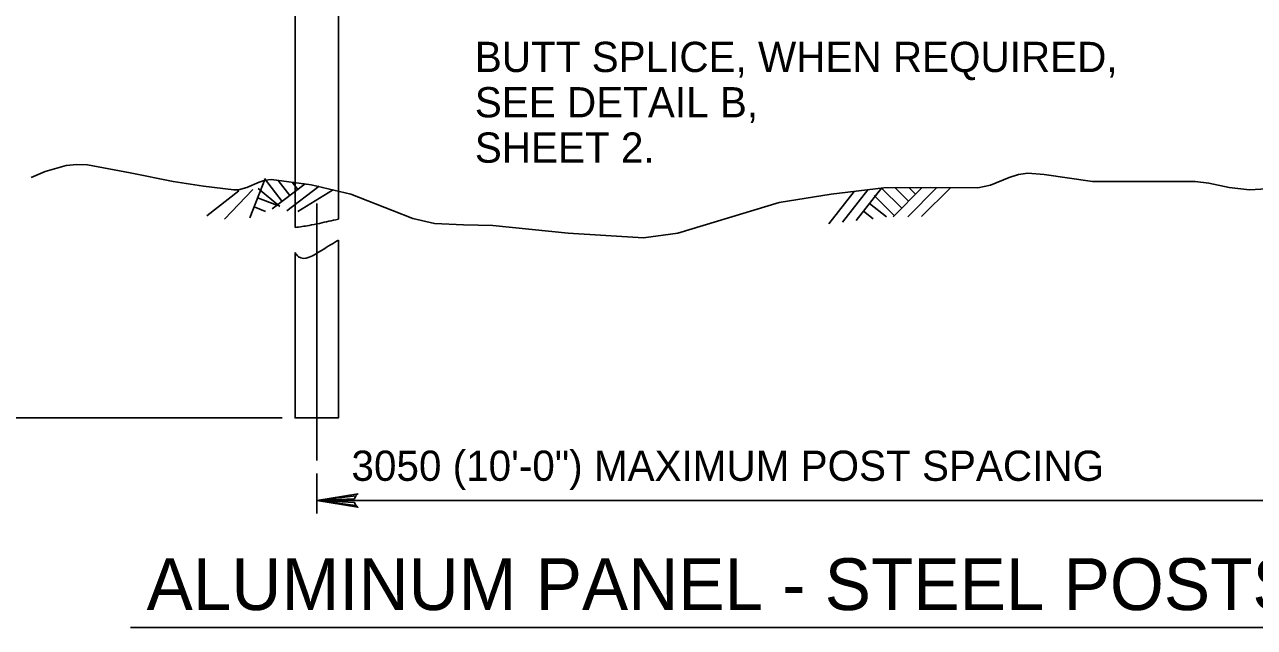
# Model space of a CAD drawing. Extents: x -4 to 901, y -468 to 720.
# Drawn here: x 119.8 to 256.4, y 539.9 to 606.9 of the extents above; entities that cross this region are included whole.
import ezdxf

# ---------------------------------------------------------------- set-up
doc = ezdxf.new("R2010")
doc.units = 0
doc.layers.add('2', color=7, linetype='Continuous')
doc.layers.add('3', color=7, linetype='Continuous')

msp = doc.modelspace()

# ---------------------------------------------------------------- linework, layer by layer
at = {"layer": '2'}
for p, q in [((144.8465, 585.443125), (146.5025, 589.703125)), ((146.4605, 589.811125), (148.4265, 587.255125)), ((147.3445, 586.437125), (150.9865, 589.237125)), ((148.0025, 589.609125), (149.2845, 587.943125)), ((148.9725, 586.225125), (152.5565, 588.981125)), ((149.5625, 589.407125), (150.1725, 588.611125)), ((214.9625, 588.779125), (217.2585, 586.513125)), ((216.2965, 585.555125), (219.5225, 588.827125)), ((216.5165, 588.789125), (218.0125, 587.313125)), ((217.9385, 585.567125), (221.1145, 588.785125)), ((218.0885, 588.799125), (218.8025, 588.095125)), ((140.0685, 585.653125), (143.6425, 588.461125)), ((142.0305, 585.287125), (145.1685, 588.607125)), ((145.7145, 587.675125), (147.9465, 586.807125)), ((145.7605, 588.723125), (148.1825, 586.705125)), ((150.1985, 586.157125), (154.0485, 588.527125)), ((209.1765, 584.789125), (211.9805, 588.365125)), ((210.6685, 584.969125), (213.4885, 588.565125)), ((212.2125, 585.157125), (215.0325, 588.753125)), ((214.1905, 587.927125), (216.4345, 585.713125)), ((219.4485, 585.591125), (222.6685, 588.767125)), ((145.3165, 586.651125), (146.5905, 586.155125)), ((152.2805, 587.057125), (152.2805, 558.467125)), ((213.0125, 586.175125), (214.0885, 585.331125)), ((213.6905, 587.041125), (215.5765, 585.563125)), ((148.4405, 563.195125), (93.0485, 563.195125)), ((152.2805, 557.027125), (152.2805, 552.577125)), ((152.2805, 554.017125), (272.2805, 554.017125))]:
    msp.add_line(p, q, dxfattribs=at)
for points in [[(149.8805, 584.369125), (149.8805, 608.795125)], [(154.6805, 608.795125), (154.6805, 585.299125)], [(120.5505, 589.941125), (122.1125, 590.585125), (124.4605, 591.259125), (125.6365, 591.389125), (126.8165, 591.333125), (131.5745, 590.443125), (136.3345, 589.477125), (139.7005, 588.951125), (143.0665, 588.549125), (143.5965, 588.563125), (144.5125, 588.827125), (145.8745, 589.425125), (146.5565, 589.647125), (147.2445, 589.709125), (151.6525, 589.133125), (156.0645, 588.083125), (160.6805, 586.257125), (162.9705, 585.365125), (165.3505, 584.833125), (168.5985, 584.679125), (171.8505, 584.601125), (180.2165, 583.751125), (188.5645, 583.209125), (192.3805, 583.733125), (203.6525, 587.155125), (209.4425, 588.075125), (215.2585, 588.781125), (220.4845, 588.815125), (225.7045, 588.781125), (227.1145, 589.091125), (229.1785, 589.927125), (230.2165, 590.267125), (231.2745, 590.405125), (233.0665, 590.271125), (238.4705, 589.477125), (244.1645, 589.499125), (249.8465, 589.477125), (251.3585, 589.291125), (253.6185, 588.825125), (255.8805, 588.549125), (260.2905, 588.813125)], [(154.6805, 582.977125), (154.6805, 563.195125), (149.8805, 563.195125), (149.8805, 581.585125)], [(156.6405, 553.471125), (156.4765, 553.785125), (152.2805, 554.017125), (156.6405, 553.471125), (156.8625, 553.279125), (152.2805, 554.017125), (156.4745, 554.225125), (156.6265, 554.537125), (152.2805, 554.017125), (156.8625, 554.745125), (156.6265, 554.537125)]]:
    msp.add_lwpolyline(points, dxfattribs=at)
for points in [[(149.8805, 584.369125), (151.4225, 584.601125), (152.5825, 584.833125), (154.6805, 585.299125)], [(149.8805, 581.585125), (150.2625, 581.119125), (152.8165, 581.817125), (154.6805, 582.977125)]]:
    msp.add_spline(points, degree=3, dxfattribs=at)
at = {"layer": '3'}
msp.add_line((131.6125, 539.912125), (293.3405, 539.912125), dxfattribs=at)

# ---------------------------------------------------------------- texts
for s, height, p in [('BUTT SPLICE, WHEN REQUIRED,', 3.359988, (169.8425, 601.657125)), ('SEE DETAIL B,', 3.359988, (169.8425, 596.617125)), ('SHEET 2.', 3.359988, (169.8425, 591.577125)), ('3050 (10\'-0") MAXIMUM POST SPACING', 3.36, (156.1375, 556.207875)), ('ALUMINUM PANEL - STEEL POSTS', 5.76, (133.3825, 541.839125))]:
    msp.add_text(s, height=height, dxfattribs=at).set_placement(p)

doc.saveas('drawing.dxf')
